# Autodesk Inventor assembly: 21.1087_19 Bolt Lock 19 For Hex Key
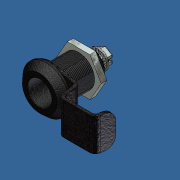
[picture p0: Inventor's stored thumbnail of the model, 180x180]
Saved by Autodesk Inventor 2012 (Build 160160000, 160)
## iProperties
Created: 2007-03
Part Number: 21.1087_19 Bolt Lock 19 For Hex Key
Document SubType Name: Assembly
Designer: Andy Moles
Mass: 183.899 g
Surface Area: 234.354 cm^2
Volume: 25.7571 cm^3
Density: 7.13977 g/cm^3
Translation Standard: STEP AP214IS
File Name: 1000-U405_ASM
Preprocessor: PRO/ENGINEER BY PARAMETRIC TECHNOLOGY CORPORATION, 2003200
Postprocessor: Build: 344b, Release: 11 SP2 - Date: Fri 08/18/2006
Sent Units: MILLIMETERS
Uncertainty: 0.01136958734563
Author: Andy Moles
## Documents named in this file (5)
- C:\Andys Backup Data\ANDY'S INVENTOR\INVENTOR LIBRARIES\PARTS LIBRARY\HANDLES LOCKS STOPS\21.1087_19 Bolt Lock 19 For Hex Key.iam
- C:\Andys Backup Data\ANDY'S INVENTOR\INVENTOR LIBRARIES\PARTS LIBRARY\HANDLES LOCKS STOPS\SUBCOMPONENTS\EMKA SUBCOMPONENTS\1000-02.ipt
- C:\Andys Backup Data\ANDY'S INVENTOR\INVENTOR LIBRARIES\PARTS LIBRARY\HANDLES LOCKS STOPS\SUBCOMPONENTS\EMKA SUBCOMPONENTS\1000-107.ipt
- C:\Andys Backup Data\ANDY'S INVENTOR\INVENTOR LIBRARIES\PARTS LIBRARY\HANDLES LOCKS STOPS\SUBCOMPONENTS\EMKA SUBCOMPONENTS\1000-359 FINGER PULL.ipt
- C:\Andys Backup Data\ANDY'S INVENTOR\INVENTOR LIBRARIES\PARTS LIBRARY\HANDLES LOCKS STOPS\SUBCOMPONENTS\EMKA SUBCOMPONENTS\1000-U96 10mm HEX CHROME INSERT.iam
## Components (4 placed, 4 different names)
1. 1000-02 — Mate:3, Mate:6, Angle:1
2. 1000-107:1 — Mate:1, Mate:2, Mate:3, Mate:5, Flush:2, Flush:3, Flush:4, Angle:1, Angle:2, Angle:3
3. 1000-359 FINGER PULL:1 — Mate:1, Mate:2, Mate:6, Mate:7, Angle:3
4. 1000-U96 10mm HEX CHROME INSERT:1 [sub-assembly] — Mate:5, Flush:2, Angle:2
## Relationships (12: Mate 6, Flush 3, Angle 3)
- Mate:1: 1000-107:1 ↔ 1000-359 FINGER PULL:1
- Mate:2: 1000-107:1 ↔ 1000-359 FINGER PULL:1
- Mate:3: 1000-02 ↔ 1000-107:1
- Mate:5: 1000-107:1 ↔ 1000-U96 10mm HEX CHROME INSERT:1
- Flush:2: 1000-107:1 ↔ 1000-U96 10mm HEX CHROME INSERT:1
- Mate:6: 1000-02 ↔ 1000-359 FINGER PULL:1
- Flush:3: 1000-107:1
- Mate:7: 1000-359 FINGER PULL:1
- Flush:4: 1000-107:1
- Angle:1: 1000-02 ↔ 1000-107:1
- Angle:2: 1000-107:1 ↔ 1000-U96 10mm HEX CHROME INSERT:1
- Angle:3: 1000-107:1 ↔ 1000-359 FINGER PULL:1
